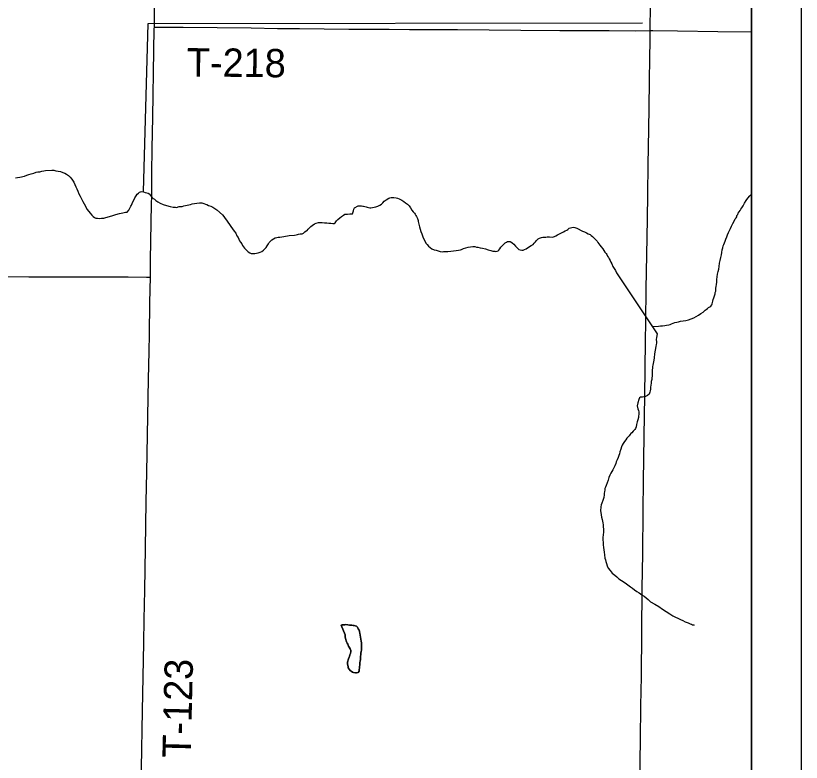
# Model space of a CAD drawing. Extents: x 0 to 64.8, y -5 to 22.
# Drawn here: x 7.424 to 9, y 15.783 to 17.279 of the extents above; entities that cross this region are included whole.
import ezdxf

# ---------------------------------------------------------------- set-up
doc = ezdxf.new("R2010")
doc.units = 0
for name, color, linetype in [('GM_X_Adjacent_County', 7, 'Continuous'), ('GM_X_County', 7, 'Continuous'), ('GM_X_County_Road', 7, 'Continuous'), ('GM_X_Minor_Lake', 7, 'Continuous'), ('GM_X_Minor_River', 7, 'Continuous'), ('GM_X_Township', 7, 'Continuous'), ('GM_X_Township_Road', 7, 'Continuous'), ('GM_X_Township_Road_Text', 7, 'Continuous'), ('SH_Data', 7, 'Continuous')]:
    doc.layers.add(name, color=color, linetype=linetype)

msp = doc.modelspace()

# ---------------------------------------------------------------- linework, layer by layer
at = {"layer": 'GM_X_Adjacent_County'}
msp.add_lwpolyline([(2.1, 19.9176), (2.1, 14.1), (8.9, 14.1), (8.9, 19.781)], dxfattribs=at)
at = {"layer": 'GM_X_County'}
msp.add_lwpolyline([(2.1, 19.9176), (2.1, 14.1), (8.9, 14.1), (8.9, 19.781)], dxfattribs=at)
at = {"layer": 'GM_X_County_Road'}
for points in [[(8.6971, 17.2493), (8.6972, 17.2568), (8.6976, 17.2941), (8.6982, 17.3531), (8.6998, 17.4557), (8.7017, 17.5707), (8.7026, 17.6298), (8.7037, 17.7012), (8.7047, 17.7527)], [(8.6759, 15.7407), (8.6759, 15.7433), (8.6775, 15.8272), (8.6784, 15.8956), (8.6794, 15.9546), (8.6811, 16.1318), (8.6821, 16.2002), (8.6829, 16.2872), (8.6834, 16.3463), (8.6846, 16.4364), (8.6859, 16.5172), (8.6876, 16.626), (8.6881, 16.6664), (8.6892, 16.7316), (8.6901, 16.8), (8.6916, 16.8715), (8.6925, 16.9212), (8.6931, 16.9802), (8.6941, 17.0517), (8.6949, 17.0952), (8.6957, 17.1481), (8.6965, 17.1947), (8.6968, 17.2288), (8.6971, 17.2493)]]:
    msp.add_lwpolyline(points, dxfattribs=at)
at = {"layer": 'GM_X_Minor_Lake'}
for points in [[(8.114, 15.9747), (8.1144, 15.977), (8.1145, 15.9796), (8.1146, 15.9823), (8.1154, 15.9853), (8.1158, 15.9883), (8.1159, 15.991), (8.1159, 15.9933), (8.116, 15.9955), (8.1164, 15.9982), (8.1169, 16.0016), (8.1173, 16.0046), (8.1178, 16.0073), (8.1178, 16.0099), (8.1179, 16.013), (8.118, 16.0156), (8.118, 16.0187), (8.1177, 16.0221), (8.1174, 16.0255), (8.1168, 16.0293), (8.1148, 16.0411), (8.1141, 16.0438), (8.1137, 16.0457), (8.113, 16.0476), (8.1115, 16.0503), (8.1097, 16.0534), (8.1079, 16.0554), (8.1052, 16.0562), (8.1033, 16.057), (8.101, 16.057), (8.0988, 16.0575), (8.0942, 16.0576), (8.0908, 16.0584), (8.0866, 16.0585), (8.0843, 16.0582), (8.0821, 16.0582), (8.079, 16.0579), (8.0771, 16.0572)], [(8.0771, 16.0572), (8.079, 16.0579), (8.0821, 16.0582), (8.0843, 16.0582), (8.0866, 16.0585), (8.0908, 16.0584), (8.0942, 16.0576), (8.0988, 16.0575), (8.101, 16.057), (8.1033, 16.057), (8.1052, 16.0562), (8.1079, 16.0554), (8.1097, 16.0534), (8.1115, 16.0503), (8.113, 16.0476), (8.1137, 16.0457), (8.1141, 16.0438), (8.1148, 16.0411), (8.1168, 16.0293), (8.1174, 16.0255), (8.1177, 16.0221), (8.118, 16.0187), (8.118, 16.0156), (8.1179, 16.013), (8.1178, 16.0099), (8.1178, 16.0073), (8.1173, 16.0046), (8.1169, 16.0016), (8.1164, 15.9982), (8.116, 15.9955), (8.1159, 15.9933), (8.1159, 15.991), (8.1158, 15.9883), (8.1154, 15.9853), (8.1146, 15.9823), (8.1145, 15.9796), (8.1144, 15.977), (8.114, 15.9747), (8.1139, 15.9713), (8.1135, 15.9682), (8.113, 15.9652), (8.1111, 15.9626), (8.1076, 15.9619), (8.1057, 15.9616), (8.1019, 15.9624), (8.1, 15.9629), (8.0974, 15.9652), (8.0952, 15.9668), (8.093, 15.9691), (8.0915, 15.9718), (8.0912, 15.9737), (8.0902, 15.9802), (8.0902, 15.9832), (8.0907, 15.9851), (8.0915, 15.9877), (8.0919, 15.9896), (8.0931, 15.993), (8.0939, 15.9949), (8.0948, 15.9979), (8.0956, 16.0009), (8.0964, 16.0043), (8.0965, 16.0066), (8.0954, 16.0097), (8.0932, 16.0135), (8.0921, 16.0154), (8.091, 16.0174), (8.0903, 16.0193), (8.0892, 16.0216), (8.0877, 16.0239), (8.087, 16.0262), (8.0863, 16.0285), (8.086, 16.0304), (8.0853, 16.0342), (8.0854, 16.0361), (8.085, 16.038), (8.0771, 16.0572)], [(8.0771, 16.0572), (8.085, 16.038), (8.0854, 16.0361), (8.0853, 16.0342), (8.086, 16.0304), (8.0863, 16.0285), (8.087, 16.0262), (8.0877, 16.0239), (8.0892, 16.0216), (8.0903, 16.0193), (8.091, 16.0174), (8.0921, 16.0154), (8.0932, 16.0135), (8.0954, 16.0097), (8.0965, 16.0066), (8.0964, 16.0043), (8.0956, 16.0009), (8.0948, 15.9979), (8.0939, 15.9949), (8.0931, 15.993), (8.0919, 15.9896), (8.0915, 15.9877), (8.0907, 15.9851), (8.0902, 15.9832), (8.0902, 15.9802), (8.0912, 15.9737), (8.0915, 15.9718), (8.093, 15.9691), (8.0952, 15.9668), (8.0974, 15.9652), (8.1, 15.9629), (8.1019, 15.9624), (8.1057, 15.9616), (8.1076, 15.9619), (8.1111, 15.9626), (8.113, 15.9652), (8.1135, 15.9682), (8.1139, 15.9713), (8.114, 15.9747)]]:
    msp.add_lwpolyline(points, dxfattribs=at)
at = {"layer": 'GM_X_Minor_River'}
for points in [[(7.6804, 16.9262), (7.6899, 17.2637), (8.6812, 17.2649)], [(7.424, 16.9544), (7.4282, 16.955), (7.4324, 16.9553), (7.4358, 16.956), (7.4389, 16.9567), (7.4423, 16.9574), (7.4469, 16.9592), (7.4508, 16.9606), (7.4557, 16.9624), (7.4607, 16.9638), (7.4653, 16.9652), (7.4691, 16.9659), (7.4729, 16.9665), (7.4768, 16.9672), (7.4806, 16.9683), (7.4844, 16.9689), (7.4966, 16.9698), (7.5008, 16.9693), (7.5049, 16.9685), (7.5095, 16.9676), (7.5144, 16.9668), (7.5189, 16.9651), (7.5227, 16.9635), (7.5264, 16.9612), (7.5302, 16.9588), (7.5335, 16.9557), (7.5372, 16.9514), (7.5409, 16.9456), (7.5431, 16.9407), (7.5449, 16.9364), (7.5467, 16.9318), (7.5489, 16.9272), (7.551, 16.9222), (7.5536, 16.9176), (7.5565, 16.9122), (7.5591, 16.9069), (7.5616, 16.9019), (7.5645, 16.8972), (7.5671, 16.8915), (7.5711, 16.8868), (7.5741, 16.883), (7.5771, 16.8795), (7.58, 16.8768), (7.5827, 16.8748), (7.5853, 16.8736), (7.5883, 16.8731), (7.5917, 16.8727), (7.5963, 16.873), (7.6009, 16.8732), (7.6051, 16.8747), (7.6127, 16.8768), (7.6189, 16.8785), (7.6254, 16.8807), (7.6323, 16.8828), (7.6391, 16.8842), (7.6449, 16.8852), (7.6483, 16.8855), (7.6511, 16.8892), (7.6526, 16.8922), (7.6542, 16.8948), (7.6554, 16.8975), (7.6566, 16.8997), (7.6578, 16.9024), (7.6634, 16.914), (7.6658, 16.9178), (7.6681, 16.9211), (7.6704, 16.9233), (7.6724, 16.9252), (7.6747, 16.9263), (7.6777, 16.9266), (7.6804, 16.9262), (7.6842, 16.9249), (7.6876, 16.9241), (7.6902, 16.9237)], [(7.6902, 16.9237), (7.6921, 16.9221), (7.6954, 16.9178), (7.698, 16.914), (7.7025, 16.9112), (7.7055, 16.9085), (7.7092, 16.9058), (7.7141, 16.9034), (7.7201, 16.9009), (7.7266, 16.8989), (7.7341, 16.8968), (7.7402, 16.8956), (7.7447, 16.8951), (7.7474, 16.895), (7.7501, 16.8957), (7.7524, 16.8964), (7.7554, 16.8967), (7.7584, 16.897), (7.7615, 16.8977), (7.7649, 16.8984), (7.768, 16.8991), (7.7714, 16.8998), (7.7749, 16.9009), (7.7783, 16.9019), (7.7829, 16.903), (7.7875, 16.9036), (7.7932, 16.9039), (7.7974, 16.9038), (7.8015, 16.9029), (7.8049, 16.9017), (7.808, 16.9005), (7.8113, 16.8989), (7.8159, 16.8973), (7.8196, 16.8953), (7.8238, 16.8929), (7.8275, 16.8902), (7.8391, 16.88), (7.8416, 16.8766), (7.8442, 16.8727), (7.8472, 16.8692), (7.8501, 16.865), (7.8531, 16.8607), (7.856, 16.8565), (7.8593, 16.8518), (7.8626, 16.8472), (7.8656, 16.843), (7.8678, 16.838), (7.8703, 16.8345), (7.8722, 16.831), (7.8736, 16.828), (7.8755, 16.8249), (7.8777, 16.8218), (7.8795, 16.8187), (7.8813, 16.816), (7.8832, 16.8129), (7.8858, 16.8102), (7.8884, 16.8075), (7.8906, 16.8056), (7.894, 16.8036), (7.8966, 16.8028), (7.9, 16.8023), (7.9038, 16.8022), (7.9077, 16.8029), (7.9107, 16.8036), (7.9145, 16.805), (7.918, 16.8068), (7.9211, 16.809), (7.9238, 16.8116), (7.9266, 16.8146), (7.9289, 16.818), (7.9301, 16.8199), (7.9313, 16.8221), (7.9329, 16.8244), (7.9348, 16.8262), (7.9364, 16.8281), (7.9383, 16.8299), (7.9414, 16.8321), (7.9448, 16.8336), (7.9479, 16.8347), (7.951, 16.835), (7.954, 16.8353), (7.9582, 16.8359), (7.962, 16.8366), (7.9658, 16.8373), (7.9693, 16.838), (7.9731, 16.8386), (7.9838, 16.8395), (7.9868, 16.8402), (7.9895, 16.8406), (7.9918, 16.8409), (7.9948, 16.8416), (7.999, 16.8422), (8.0013, 16.843), (8.0044, 16.8459), (8.0071, 16.8478), (8.0091, 16.8489), (8.011, 16.8515), (8.0134, 16.8541), (8.0161, 16.8563), (8.0192, 16.8589), (8.0234, 16.8618)], [(8.8697, 16.8743), (8.8705, 16.8762), (8.8709, 16.8785), (8.8725, 16.8807), (8.8737, 16.8834), (8.8753, 16.886), (8.8773, 16.889), (8.8788, 16.8912), (8.8808, 16.8942), (8.8836, 16.8983), (8.8863, 16.9036), (8.8895, 16.9088), (8.893, 16.9137), (8.8965, 16.9182), (8.9, 16.9217)], [(8.0234, 16.8618), (8.0273, 16.8636), (8.0319, 16.8643), (8.0353, 16.8646), (8.0391, 16.8645), (8.0436, 16.864), (8.0482, 16.8639), (8.0527, 16.8634), (8.0565, 16.863), (8.0603, 16.8629), (8.063, 16.8628), (8.0653, 16.8639), (8.068, 16.8677), (8.0708, 16.8706), (8.0743, 16.874), (8.0781, 16.8769), (8.082, 16.8795), (8.0847, 16.881), (8.0866, 16.8813), (8.0897, 16.8816), (8.0946, 16.8819), (8.0976, 16.8818), (8.0996, 16.8821), (8.1007, 16.884), (8.1016, 16.8878), (8.1024, 16.8912), (8.1036, 16.8942), (8.1113, 16.8982), (8.1132, 16.8982), (8.1159, 16.8981), (8.1178, 16.8981), (8.1204, 16.8976), (8.1223, 16.8972), (8.1246, 16.8968), (8.1276, 16.896), (8.1295, 16.8952), (8.1318, 16.8947), (8.1344, 16.8943), (8.1367, 16.8942), (8.1398, 16.8945), (8.1436, 16.8952), (8.147, 16.8959), (8.1505, 16.8973), (8.1547, 16.8991), (8.1582, 16.9013), (8.1609, 16.9039), (8.1632, 16.9077), (8.1671, 16.9103), (8.1725, 16.9132), (8.1748, 16.9139), (8.1775, 16.9146), (8.1801, 16.9149), (8.1828, 16.9148), (8.1877, 16.9144), (8.19, 16.9135), (8.1934, 16.9119), (8.199, 16.9092), (8.2031, 16.9068), (8.2065, 16.9041), (8.2103, 16.9017), (8.2136, 16.8982), (8.2165, 16.894), (8.2191, 16.8893), (8.2217, 16.8859), (8.2243, 16.8831), (8.2258, 16.8812), (8.2272, 16.8789), (8.2283, 16.8766), (8.2305, 16.8727), (8.2309, 16.8708), (8.2316, 16.8689), (8.2319, 16.8666), (8.2343, 16.8559), (8.2357, 16.8514), (8.2371, 16.8464), (8.239, 16.8422), (8.2411, 16.836), (8.2429, 16.8311), (8.2455, 16.8268), (8.2473, 16.8234), (8.2495, 16.8203), (8.2521, 16.8172), (8.2554, 16.8144), (8.2592, 16.8121), (8.2637, 16.8101), (8.2675, 16.8089), (8.2716, 16.8076), (8.2758, 16.8064), (8.2796, 16.8059), (8.2823, 16.8062), (8.2841, 16.8062), (8.2872, 16.8065), (8.2914, 16.8068), (8.2971, 16.8074), (8.3028, 16.8081), (8.3078, 16.8087), (8.3127, 16.809), (8.3165, 16.8096), (8.3188, 16.8104), (8.3227, 16.8125), (8.3273, 16.814)], [(8.7009, 16.6561), (8.7139, 16.6571), (8.7177, 16.6574), (8.7219, 16.6577), (8.7261, 16.6584), (8.7299, 16.659), (8.7341, 16.6597), (8.7371, 16.6604), (8.7394, 16.6615), (8.7429, 16.6629), (8.7463, 16.664), (8.7501, 16.6646), (8.7536, 16.6657), (8.7578, 16.6668), (8.7631, 16.6678), (8.7685, 16.6684), (8.7735, 16.6698), (8.7792, 16.6712), (8.7846, 16.6734), (8.7892, 16.6759), (8.7938, 16.6789), (8.7985, 16.6822), (8.8031, 16.6847), (8.8058, 16.6873), (8.8074, 16.6892), (8.8093, 16.6903), (8.8116, 16.6925), (8.8139, 16.6944), (8.8166, 16.6954), (8.8186, 16.6969), (8.8205, 16.6995), (8.8213, 16.7018), (8.8218, 16.7041), (8.8226, 16.7067), (8.823, 16.7105), (8.8243, 16.7135), (8.8271, 16.7218), (8.8275, 16.7241), (8.8284, 16.7267), (8.8288, 16.7297), (8.8289, 16.7328), (8.8293, 16.7362), (8.8298, 16.7404), (8.8303, 16.7449), (8.8304, 16.7502), (8.8313, 16.7555), (8.8322, 16.7608), (8.833, 16.7661), (8.8343, 16.7714), (8.8352, 16.7767), (8.8361, 16.7831), (8.8373, 16.7884), (8.8386, 16.7945), (8.8399, 16.7998), (8.8408, 16.8047), (8.8416, 16.8096), (8.8425, 16.8138), (8.8433, 16.8176), (8.8445, 16.8206), (8.8458, 16.824), (8.8473, 16.827), (8.8486, 16.8311), (8.8506, 16.836), (8.8522, 16.8401), (8.8538, 16.8443), (8.8562, 16.8484), (8.8582, 16.8529), (8.8602, 16.8574), (8.863, 16.8627), (8.8657, 16.8676), (8.8677, 16.8717), (8.8697, 16.8743)], [(8.3273, 16.814), (8.3319, 16.8154), (8.3365, 16.816), (8.3414, 16.8163), (8.3452, 16.8162), (8.3486, 16.8154), (8.3516, 16.8149), (8.3558, 16.8141), (8.3607, 16.8132), (8.3664, 16.8119), (8.3717, 16.8099), (8.3774, 16.8087), (8.3815, 16.8074), (8.3853, 16.807), (8.3876, 16.8065), (8.3899, 16.8069), (8.3918, 16.8076), (8.3937, 16.8094), (8.3953, 16.8121), (8.3973, 16.815), (8.3992, 16.8169), (8.4062, 16.824), (8.4085, 16.8251), (8.4108, 16.8265), (8.4139, 16.8268), (8.4158, 16.8264), (8.4177, 16.8256), (8.4199, 16.8237), (8.4236, 16.8209), (8.427, 16.8174), (8.4292, 16.8143), (8.4318, 16.8128), (8.4337, 16.8108), (8.4363, 16.8096), (8.4393, 16.8092), (8.4424, 16.8091), (8.4451, 16.8102), (8.4485, 16.812), (8.4532, 16.8149), (8.4582, 16.8182), (8.462, 16.8204), (8.4644, 16.823), (8.4667, 16.8256), (8.4683, 16.8279), (8.4702, 16.8297), (8.4726, 16.8316), (8.4752, 16.833), (8.4787, 16.8345), (8.4818, 16.8352), (8.484, 16.8351), (8.4878, 16.8354), (8.4905, 16.8357), (8.4947, 16.8356), (8.5004, 16.8355), (8.5031, 16.8358), (8.505, 16.8366), (8.5077, 16.838), (8.5111, 16.8398), (8.5154, 16.8416), (8.5192, 16.8438), (8.5231, 16.846), (8.5265, 16.8479), (8.5296, 16.8493), (8.5315, 16.8508), (8.5343, 16.853), (8.5369, 16.8541), (8.5396, 16.8548), (8.5427, 16.8551), (8.5461, 16.8543), (8.5498, 16.853), (8.5611, 16.8475), (8.5653, 16.8458), (8.569, 16.8439), (8.5724, 16.8419), (8.5765, 16.8403), (8.5788, 16.8383), (8.5814, 16.8364), (8.584, 16.834), (8.5862, 16.8317), (8.5885, 16.8294), (8.5903, 16.827), (8.5922, 16.8243), (8.594, 16.822), (8.5962, 16.8189), (8.5988, 16.8158), (8.6018, 16.812), (8.604, 16.8085), (8.6062, 16.8054), (8.6084, 16.8027), (8.6099, 16.8004), (8.6113, 16.7973), (8.6132, 16.7946), (8.6146, 16.7915), (8.6164, 16.7885), (8.6183, 16.785), (8.6201, 16.7815), (8.6223, 16.7766), (8.6248, 16.7727), (8.6274, 16.7681), (8.6296, 16.7639), (8.691, 16.6712)], [(8.691, 16.6712), (8.7108, 16.6412), (8.7095, 16.634), (8.7091, 16.6299), (8.7093, 16.6257), (8.7093, 16.6226), (8.7088, 16.62), (8.708, 16.6162), (8.7067, 16.609), (8.7054, 16.6015), (8.7052, 16.5935), (8.7043, 16.5886), (8.7035, 16.5852), (8.703, 16.5818), (8.7022, 16.5784), (8.7018, 16.5757), (8.7013, 16.5727), (8.7008, 16.5693), (8.7008, 16.5658), (8.7007, 16.5621), (8.7006, 16.5567), (8.7005, 16.5533), (8.7, 16.5499), (8.6992, 16.5461), (8.6987, 16.5427), (8.6983, 16.5386), (8.6978, 16.5344), (8.6973, 16.5306), (8.6969, 16.5272), (8.6964, 16.5245), (8.6956, 16.5223), (8.6948, 16.5204), (8.6917, 16.5178), (8.6875, 16.516), (8.684, 16.5149), (8.6814, 16.5146), (8.6795, 16.5147), (8.6776, 16.5147), (8.6756, 16.5129), (8.6744, 16.5095), (8.672, 16.5031), (8.6711, 16.4974), (8.6721, 16.4913), (8.6732, 16.4878), (8.6739, 16.4852), (8.6742, 16.4833), (8.6732, 16.4738), (8.6724, 16.4692), (8.6711, 16.4651), (8.6698, 16.4594), (8.669, 16.4553), (8.6678, 16.4519), (8.6662, 16.4496), (8.6631, 16.4463), (8.66, 16.4429), (8.658, 16.4414), (8.6561, 16.4392), (8.6545, 16.437), (8.6526, 16.4347), (8.6502, 16.4321), (8.6483, 16.4291), (8.6455, 16.4254), (8.6428, 16.4217), (8.6408, 16.4183), (8.6396, 16.4149), (8.6379, 16.41), (8.6363, 16.4051), (8.6351, 16.4006), (8.6338, 16.3972), (8.6326, 16.3934), (8.631, 16.3889), (8.629, 16.3851), (8.6278, 16.3817), (8.6258, 16.3768), (8.6238, 16.3727), (8.6218, 16.3689), (8.6198, 16.3656), (8.6178, 16.3622), (8.6162, 16.3581), (8.6142, 16.3532), (8.6126, 16.3479), (8.6109, 16.343), (8.6089, 16.3377), (8.6073, 16.3339), (8.6061, 16.3313), (8.6057, 16.3287), (8.6052, 16.3249), (8.6048, 16.3222), (8.6047, 16.3188), (8.6038, 16.3131), (8.6021, 16.3071), (8.6001, 16.3022), (8.5989, 16.2984), (8.5981, 16.2946), (8.5971, 16.2867), (8.5978, 16.2833), (8.5985, 16.2783), (8.5995, 16.2737), (8.6005, 16.2695), (8.6016, 16.2657), (8.6023, 16.2623)], [(8.6023, 16.2623), (8.6026, 16.2588), (8.6029, 16.255), (8.6031, 16.2489), (8.603, 16.2436), (8.6025, 16.2383), (8.602, 16.233), (8.6023, 16.2285), (8.6025, 16.2231), (8.6028, 16.2182), (8.6034, 16.2132), (8.6037, 16.2087), (8.6044, 16.2037), (8.6054, 16.1984), (8.606, 16.1919), (8.6071, 16.1885), (8.6077, 16.185), (8.6092, 16.1808), (8.6106, 16.1762), (8.6128, 16.172), (8.6165, 16.167), (8.6209, 16.1619), (8.6258, 16.1576), (8.6302, 16.1541), (8.6343, 16.1506), (8.6396, 16.1471), (8.6471, 16.142), (8.6523, 16.1381), (8.6572, 16.1342), (8.6617, 16.1314), (8.6658, 16.1283), (8.6703, 16.1251), (8.6748, 16.122), (8.68, 16.1184), (8.6849, 16.1153), (8.689, 16.1122), (8.6931, 16.1087), (8.6979, 16.1044), (8.7066, 16.0996), (8.7141, 16.0945), (8.7219, 16.0894), (8.729, 16.0847), (8.7362, 16.0803), (8.7425, 16.0764), (8.7576, 16.0685), (8.7621, 16.0668), (8.767, 16.0644), (8.773, 16.062), (8.7768, 16.0604), (8.7798, 16.0592), (8.7817, 16.0584), (8.7843, 16.058), (8.7851, 16.0576), (8.7855, 16.058)]]:
    msp.add_lwpolyline(points, dxfattribs=at)
at = {"layer": 'GM_X_Township'}
msp.add_lwpolyline([(5.5757, 14.1), (8.9, 14.1), (8.9, 19.781)], dxfattribs=at)
at = {"layer": 'GM_X_Township_Road'}
for points in [[(7.7025, 17.2565), (7.7027, 17.2806), (7.7033, 17.3085), (7.7064, 17.439), (7.7079, 17.4918), (7.712, 17.6938), (7.7134, 17.7501), (7.7138, 17.7613)], [(7.6945, 16.7553), (7.6945, 16.7586), (7.6951, 16.7958), (7.6955, 16.8207), (7.6962, 16.8704), (7.6966, 16.8953), (7.6972, 16.9232), (7.6977, 16.9636), (7.6982, 17.0133), (7.6993, 17.0755), (7.7012, 17.2091), (7.7024, 17.2526), (7.7025, 17.2565)], [(7.7025, 17.2565), (7.7073, 17.2565), (7.7104, 17.2565), (7.7601, 17.2563), (7.8969, 17.2546), (7.9497, 17.2537), (7.9933, 17.2535), (8.0927, 17.2525), (8.1735, 17.2522), (8.214, 17.2517), (8.3103, 17.2512), (8.4378, 17.2503), (8.5155, 17.2498), (8.6149, 17.2493), (8.6678, 17.249), (8.6971, 17.2493)], [(8.6971, 17.2493), (8.702, 17.2493), (8.7517, 17.249), (8.8325, 17.2478), (8.9, 17.2468)], [(6.6963, 16.7621), (6.7027, 16.7622), (6.7058, 16.7623), (6.7306, 16.7619), (6.7772, 16.7617), (6.8486, 16.7615), (6.9107, 16.7609), (6.9852, 16.7599), (7.1032, 16.759), (7.1622, 16.7584), (7.2025, 16.7577), (7.2678, 16.7573), (7.3454, 16.7567), (7.4509, 16.756), (7.5192, 16.7557), (7.5441, 16.7556), (7.6497, 16.7555), (7.6869, 16.7553), (7.6945, 16.7553)], [(7.6763, 15.7559), (7.6764, 15.7704), (7.6787, 15.8854), (7.6791, 15.9196), (7.6817, 16.0221), (7.6824, 16.0687), (7.6831, 16.1278), (7.6846, 16.2117), (7.6864, 16.3049), (7.6873, 16.3639), (7.6908, 16.5504), (7.6918, 16.6063), (7.6925, 16.6405), (7.6936, 16.7026), (7.6939, 16.7306), (7.6945, 16.7553)]]:
    msp.add_lwpolyline(points, dxfattribs=at)
at = {"layer": 'SH_Data'}
for p, q in [((9, 21), (9, 14)), ((8.9, 20.9), (8.9, 14.1))]:
    msp.add_line(p, q, dxfattribs=at)

# ---------------------------------------------------------------- texts
at = {"layer": 'GM_X_Township_Road_Text'}
for s, rotation, p in [('T-218', 359.4386, (7.7674, 17.1575)), ('T-123', 88.5955, (7.7753, 15.7909))]:
    msp.add_text(s, height=0.05682, rotation=rotation, dxfattribs=at).set_placement(p)

doc.saveas('drawing.dxf')
